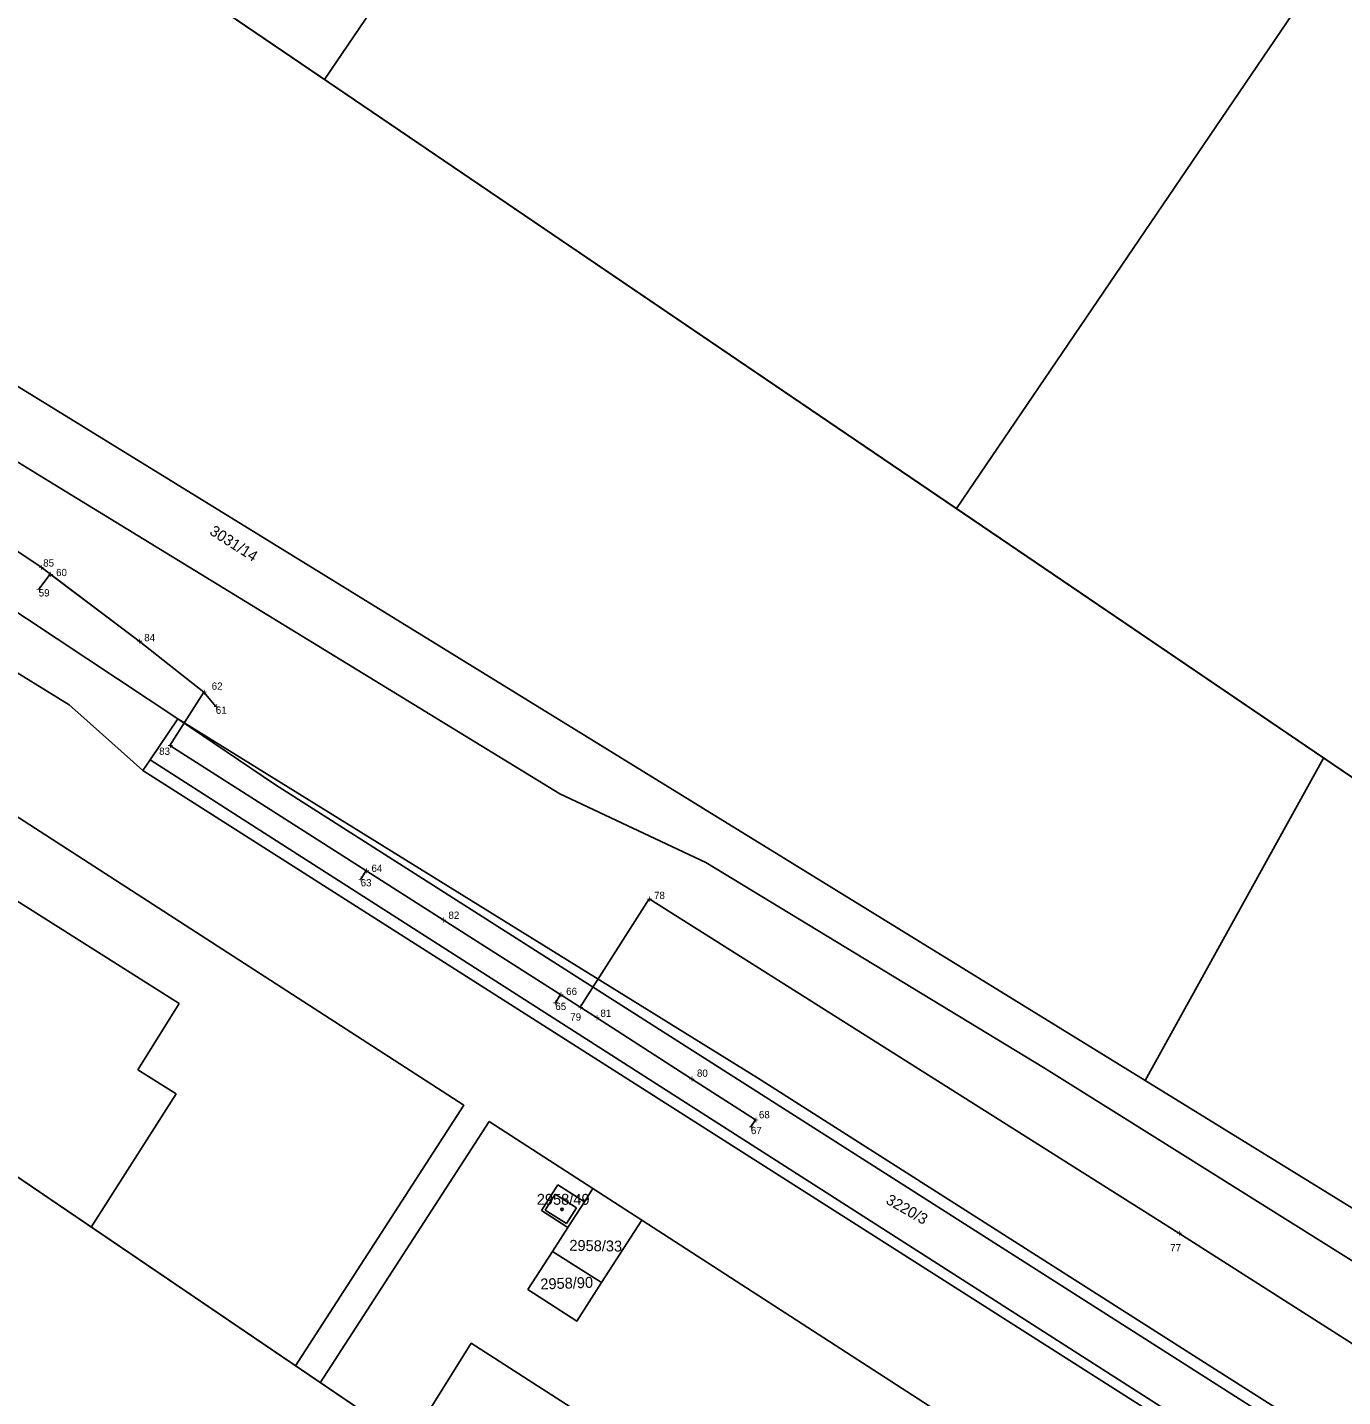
# Model space of a CAD drawing. Extents: x -621058 to -620023, y -1122866 to -1122030.
# Drawn here: x -620841.8 to -620661, y -1122451.9 to -1122263.7 of the extents above; entities that cross this region are included whole.
import ezdxf

# ---------------------------------------------------------------- set-up
doc = ezdxf.new("R2010")
doc.units = 0
for name, color, linetype in [('060604_ROZVODY_SEE', 7, 'Continuous'), ('BODY', 7, 'Continuous'), ('BODY POPIS', 7, 'Continuous'), ('RÁMY', 7, 'Continuous'), ('UZEMNĚNÍ', 7, 'Continuous'), ('Vrstva 53', 7, 'Continuous'), ('Vrstva 55', 7, 'Continuous'), ('Vrstva 56', 7, 'Continuous'), ('Vrstva 57', 7, 'Continuous')]:
    doc.layers.add(name, color=color, linetype=linetype)

msp = doc.modelspace()

# ---------------------------------------------------------------- linework, layer by layer
at = {"layer": '060604_ROZVODY_SEE'}
for p, q in [((-620840.23, -1122340.95), (-620838.67, -1122338.88)), ((-620815.89, -1122357.08), (-620817.53, -1122355.08)), ((-620795.98, -1122380.8), (-620795.24, -1122379.63)), ((-620769.23, -1122397.79), (-620768.51, -1122396.66)), ((-620742.35, -1122414.85), (-620741.73, -1122413.88))]:
    msp.add_line(p, q, dxfattribs=at)
for points in [[(-620742.35, -1122414.85), (-620741.73, -1122413.88), (-620750.53, -1122408.25), (-620763.56, -1122399.82), (-620784.65, -1122386.39), (-620822.22, -1122362.42), (-620817.53, -1122355.08), (-620826.41, -1122348.08), (-620839.92, -1122337.94), (-620854.57, -1122328.18), (-620868.06, -1122319.69), (-620885.37, -1122308.82), (-620912.87, -1122291.53), (-620913.33, -1122292.25)], [(-620443.53, -1122595), (-620456.11, -1122587.12), (-620447.82, -1122572.96), (-620450.95, -1122571.45), (-620470.59, -1122561.48), (-620499.61, -1122545.57), (-620522.04, -1122531.47), (-620538.89, -1122521.21), (-620599.21, -1122483.22), (-620683.52, -1122429.44), (-620756.33, -1122383.52), (-620765.8, -1122398.39)]]:
    msp.add_lwpolyline(points, dxfattribs=at)
at = {"layer": 'RÁMY'}
for points in [[(-620804.4, -1122089.05), (-620717.54, -1122148.04), (-620800.97, -1122270.89), (-620887.83, -1122211.9)], [(-620717.54, -1122148.04), (-620630.68, -1122207.04), (-620714.11, -1122329.88), (-620800.97, -1122270.89)], [(-620974.7, -1122152.91), (-620106.07, -1122742.82), (-620189.51, -1122865.67), (-621058.13, -1122275.76)], [(-620630.68, -1122207.04), (-620543.82, -1122266.03), (-620627.25, -1122388.87), (-620714.11, -1122329.88)], [(-620887.83, -1122211.9), (-620106.07, -1122742.82), (-620189.51, -1122865.67), (-620971.26, -1122334.75)]]:
    msp.add_lwpolyline(points, close=True, dxfattribs=at)
at = {"layer": 'UZEMNĚNÍ'}
for p, q in [((-620815.89, -1122357.08), (-620817.53, -1122355.08)), ((-620795.98, -1122380.8), (-620795.24, -1122379.63)), ((-620769.23, -1122397.79), (-620768.51, -1122396.66))]:
    msp.add_line(p, q, dxfattribs=at)
msp.add_lwpolyline([(-620742.35, -1122414.85), (-620741.73, -1122413.88), (-620750.53, -1122408.25), (-620763.56, -1122399.82), (-620784.65, -1122386.39), (-620822.22, -1122362.42), (-620817.53, -1122355.08), (-620826.41, -1122348.08), (-620838.67, -1122338.88), (-620840.23, -1122340.95)], dxfattribs=at)
at = {"layer": 'Vrstva 53'}
for p, q in [((-620847.72, -1122320.67), (-620838.83, -1122326.12)), ((-620838.83, -1122326.12), (-620768.63, -1122369.09)), ((-620821.12, -1122358.76), (-620856.79, -1122335.14)), ((-620741.46, -1122408.09), (-620821.12, -1122358.76)), ((-620768.63, -1122369.09), (-620748.53, -1122378.52)), ((-620748.53, -1122378.52), (-620702.13, -1122406.7)), ((-620702.13, -1122406.7), (-620691.02, -1122413.66)), ((-620679.51, -1122447.56), (-620741.46, -1122408.09)), ((-620691.02, -1122413.66), (-620638.48, -1122446.57)), ((-620545.92, -1122532.26), (-620679.51, -1122447.56))]:
    msp.add_line(p, q, dxfattribs=at)
at = {"layer": 'Vrstva 55'}
for p, q in [((-620866.03, -1122298.98), (-620688.16, -1122408.5)), ((-620847.72, -1122320.67), (-620838.83, -1122326.12)), ((-620838.83, -1122326.12), (-620768.63, -1122369.09)), ((-620821.12, -1122358.76), (-620856.79, -1122335.14)), ((-620836.04, -1122356.85), (-620853.22, -1122346.25)), ((-620834.44, -1122358.28), (-620836.04, -1122356.85)), ((-620825.92, -1122365.89), (-620834.44, -1122358.28)), ((-620824.91, -1122364.39), (-620821.12, -1122358.76)), ((-620821.12, -1122358.76), (-620741.46, -1122408.09)), ((-620807.67, -1122367.84), (-620821.12, -1122358.76)), ((-620824.91, -1122364.39), (-620825.92, -1122365.89)), ((-620663.64, -1122364.16), (-620688.16, -1122408.5)), ((-620872.17, -1122365.51), (-620820.94, -1122397.9)), ((-620684.91, -1122455.63), (-620825.92, -1122365.89)), ((-620645.72, -1122471.03), (-620807.67, -1122367.84)), ((-620768.63, -1122369.09), (-620748.53, -1122378.52)), ((-620748.53, -1122378.52), (-620702.13, -1122406.7)), ((-620826.62, -1122407), (-620820.94, -1122397.9)), ((-620821.36, -1122410.31), (-620826.62, -1122407)), ((-620702.13, -1122406.7), (-620691.02, -1122413.66)), ((-620741.46, -1122408.09), (-620679.51, -1122447.56)), ((-620688.16, -1122408.5), (-620548.9, -1122494.24)), ((-620833.01, -1122428.64), (-620821.36, -1122410.31)), ((-620778.34, -1122414.11), (-620801.54, -1122450.02)), ((-620764.06, -1122423.34), (-620778.34, -1122414.11)), ((-620691.02, -1122413.66), (-620638.48, -1122446.57)), ((-620768.9, -1122422.81), (-620771.15, -1122426.36)), ((-620768.9, -1122422.81), (-620765.22, -1122425.14)), ((-620764.06, -1122423.34), (-620765.22, -1122425.14)), ((-620757.34, -1122427.68), (-620764.06, -1122423.34)), ((-620771.15, -1122426.36), (-620767.52, -1122428.7)), ((-620765.22, -1122425.14), (-620767.52, -1122428.7)), ((-620762.87, -1122436.24), (-620757.34, -1122427.68)), ((-620702.74, -1122462.95), (-620757.34, -1122427.68)), ((-620767.52, -1122428.7), (-620769.63, -1122431.96)), ((-620762.87, -1122436.24), (-620769.63, -1122431.96)), ((-620545.92, -1122532.26), (-620679.51, -1122447.56))]:
    msp.add_line(p, q, dxfattribs=at)
for points in [[(-620804.95, -1122447.7), (-620781.81, -1122411.87), (-620848.87, -1122368.55)], [(-620769.63, -1122431.96), (-620773.01, -1122437.2), (-620766.29, -1122441.54), (-620762.87, -1122436.24)], [(-620758.93, -1122466.63), (-620763.57, -1122474.01), (-620789, -1122457.71), (-620780.78, -1122444.6), (-620755.36, -1122460.94)]]:
    msp.add_lwpolyline(points, dxfattribs=at)
at = {"layer": 'Vrstva 56'}
for p, q in [((-620824.91, -1122364.39), (-620810.36, -1122373.73)), ((-620810.36, -1122373.73), (-620648.08, -1122477.56)), ((-620770.64, -1122426.28), (-620769.25, -1122424.08)), ((-620769.25, -1122424.08), (-620766.31, -1122425.96)), ((-620770.64, -1122426.28), (-620767.68, -1122428.15)), ((-620767.68, -1122428.15), (-620766.31, -1122425.96))]:
    msp.add_line(p, q, dxfattribs=at)
at = {"layer": 'Vrstva 57'}
msp.add_circle((-620768.31, -1122426.2), 0.175, dxfattribs=at)

# ---------------------------------------------------------------- texts
at = {"layer": 'BODY'}
for p in [(-620840.25, -1122338.44), (-620839, -1122339.38), (-620840.56, -1122341.45), (-620826.74, -1122348.58), (-620817.86, -1122355.58), (-620816.23, -1122357.58), (-620822.55, -1122362.92), (-620795.57, -1122380.13), (-620796.32, -1122381.3), (-620756.66, -1122384.02), (-620784.98, -1122386.89), (-620768.85, -1122397.16), (-620769.56, -1122398.29), (-620766.13, -1122398.89), (-620763.89, -1122400.32), (-620750.86, -1122408.75), (-620742.69, -1122415.35), (-620742.06, -1122414.38), (-620683.86, -1122429.94)]:
    msp.add_text('+', height=1, dxfattribs=at).set_placement(p)
at = {"layer": 'BODY POPIS'}
for s, p in [('85', (-620839.62, -1122337.84)), ('60', (-620837.85, -1122339.15)), ('59', (-620840.23, -1122341.95)), ('84', (-620825.73, -1122348.1)), ('62', (-620816.46, -1122354.77)), ('61', (-620815.89, -1122358.08)), ('83', (-620823.68, -1122363.72)), ('64', (-620794.5, -1122379.81)), ('63', (-620795.98, -1122381.8)), ('78', (-620755.67, -1122383.54)), ('82', (-620783.92, -1122386.26)), ('66', (-620767.74, -1122396.73)), ('65', (-620769.23, -1122398.79)), ('79', (-620767.18, -1122400.25)), ('81', (-620763.03, -1122399.73)), ('80', (-620749.77, -1122407.97)), ('68', (-620741.25, -1122413.67)), ('67', (-620742.35, -1122415.85)), ('77', (-620684.73, -1122431.97))]:
    msp.add_text(s, height=1, dxfattribs=at).set_placement(p)
at = {"layer": 'Vrstva 57'}
for s, rotation, p in [('3031/14', 327.3665, (-620816.87, -1122333.33)), ('3220/3', 330.3, (-620723.93, -1122425.31)), ('2958/33', 359.0608, (-620767.32, -1122431.88)), ('2958/90', 2.0095, (-620771.27, -1122437.21))]:
    msp.add_text(s, height=1.5, rotation=rotation, dxfattribs=at).set_placement(p)
msp.add_text('2958/49', height=1.5, dxfattribs=at).set_placement((-620771.78, -1122425.56))

doc.saveas('drawing.dxf')
